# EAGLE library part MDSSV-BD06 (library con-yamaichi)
YAMAICHI CONNECTOR
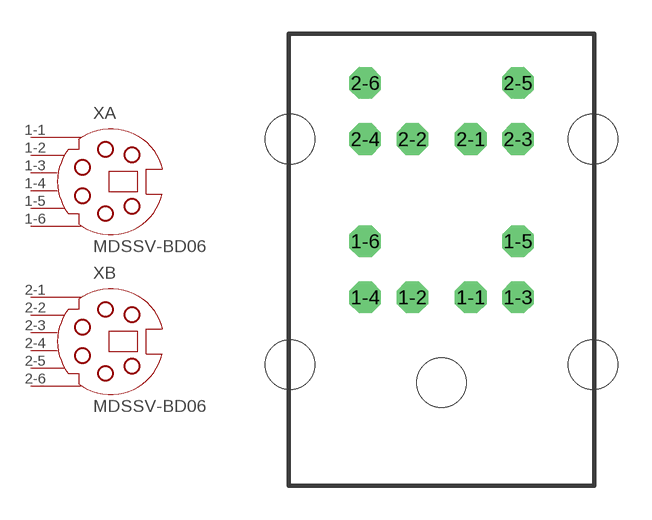
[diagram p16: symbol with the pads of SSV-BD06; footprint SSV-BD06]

Designator prefix X; gates A=SSV-BC06 B=SSV-BC06

## MDSSV-BD06 (OC_FARNELL: unknown; OC_NEWARK: unknown)  [SSV-BD06]
1-1  A:1  pas
1-2  A:2  pas
1-3  A:3  pas
1-4  A:4  pas
1-5  A:5  pas
1-6  A:6  pas
2-1  B:1  pas
2-2  B:2  pas
2-3  B:3  pas
2-4  B:4  pas
2-5  B:5  pas
2-6  B:6  pas

## Footprint SSV-BD06 (pad centres in mm)
Mini Din YAMAICHI CONNECTOR
drill 0.9 octagon: 1-1 1.3,8.5; 1-2 -1.3,8.5; 1-3 3.4,8.5; 1-4 -3.4,8.5; 1-5 3.4,11; 1-6 -3.4,11; 2-1 1.3,15.55; 2-2 -1.3,15.55; 2-3 3.4,15.55; 2-4 -3.4,15.55; 2-5 3.4,18.05; 2-6 -3.4,18.05
hole 2.2 at -6.75,15.55
hole 2.2 at 0,4.7
hole 2.2 at 6.75,15.55
hole 2.2 at -6.75,5.5
hole 2.2 at 6.75,5.5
